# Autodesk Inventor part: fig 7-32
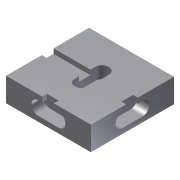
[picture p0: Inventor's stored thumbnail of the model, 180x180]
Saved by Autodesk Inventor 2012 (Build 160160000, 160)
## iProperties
Created: 2004-05
Part Number: fig 7-32
Document SubType Name: Modeling
Designer: CADCIM Technologies
Manufacturer: Standard
Standards Organization: Custom
Density: 1 g/cm^3
Material: Default
Author: CADCIM Technologies
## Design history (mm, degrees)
sketch "Sketch1"
  geometry: L1 (-30.233, -25.517)-(22.302, -25.517); L2 (22.302, -25.517)-(22.302, 25.904); L3 (22.302, 25.904)-(-30.233, 25.904); L4 (-30.233, 25.904)-(-30.233, -25.517)
  constraints: 8 end point, 2 parallel, 1 horizontal, 1 perpendicular
extrude "Extrusion1" new body sketch "Sketch1" distance "d0" = 14.75; taper "d1" = 0 deg
sketch "Sketch2"
  geometry: L1 (1.047, -5.75)-(1.047, 6.846); L2 (-7.35, 6.845)-(-7.35, -5.75); A1 r 4.198 centre (-3.152, 6.846) between (1.047, 6.846) and (-7.35, 6.845); A2 r 4.198 centre (-3.152, -5.75) between (-7.35, -5.75) and (1.047, -5.75)
  constraints: 4 end point, 4 point on circle, 4 tangent, 2 centre point, 1 parallel
extrude "Extrusion2" cut sketch "Sketch2" distance "d2" = 7.5; taper "d3" = 0 deg
sketch "Sketch3"
  geometry: L1 (-7.5, 0)-(-7.5, 12.595) reference; L2 (-7.5, 0)-(0, 0) reference; L3 (-7.5, 2.416)-(-4.537, 2.416); L4 (-4.537, 2.416)-(-4.537, 9.616); L5 (-4.537, 9.616)-(-7.5, 9.616)
  constraints: 6 end point, 2 perpendicular, 2 point on line, 1 parallel
extrude "Extrusion3" cut sketch "Sketch3" stored distance "d4" = 6.75; taper "d5" = 0 deg
sketch "Sketch4"
  geometry: L1 (1.047, -5.75)-(1.047, 6.846); L2 (-7.35, 6.845)-(-7.35, -5.75); A1 r 4.198 centre (-3.152, 6.846) between (1.047, 6.846) and (-7.35, 6.845); A2 r 4.198 centre (-3.152, -5.75) between (-7.35, -5.75) and (1.047, -5.75)
  constraints: 4 end point, 4 point on circle, 4 tangent, 2 centre point, 1 parallel
extrude "Extrusion4" cut sketch "Sketch4" taper "d7" = 0 deg; distance "d8" = 7.5
sketch "Sketch5"
  geometry: L1 (-7.5, 0)-(-7.5, 12.595) reference; L2 (-7.5, 0)-(0, 0) reference; L3 (-7.5, 2.416)-(-4.537, 2.416); L4 (-4.537, 2.416)-(-4.537, 9.616); L5 (-4.537, 9.616)-(-7.5, 9.616)
  constraints: 6 end point, 2 perpendicular, 2 point on line, 1 parallel
extrude "Extrusion5" cut sketch "Sketch5" taper "d10" = 0 deg; stored distance "d11" = 6.75
sketch "Sketch6"
  geometry: L1 (1.047, -5.75)-(1.047, 6.846); L2 (-7.35, 6.845)-(-7.35, -5.75); A1 r 4.198 centre (-3.152, 6.846) between (1.047, 6.846) and (-7.35, 6.845); A2 r 4.198 centre (-3.152, -5.75) between (-7.35, -5.75) and (1.047, -5.75)
  constraints: 4 end point, 4 point on circle, 4 tangent, 2 centre point, 1 parallel
extrude "Extrusion6" cut sketch "Sketch6" taper "d13" = 0 deg; distance "d14" = 7.5
sketch "Sketch7"
  geometry: L1 (-7.5, 0)-(-7.5, 12.595) reference; L2 (-7.5, 0)-(0, 0) reference; L3 (-7.5, 2.416)-(-4.537, 2.416); L4 (-4.537, 2.416)-(-4.537, 9.616); L5 (-4.537, 9.616)-(-7.5, 9.616)
  constraints: 6 end point, 2 perpendicular, 2 point on line, 1 parallel
extrude "Extrusion7" cut sketch "Sketch7" taper "d16" = 0 deg; stored distance "d17" = 6.75
body "Solid1"
